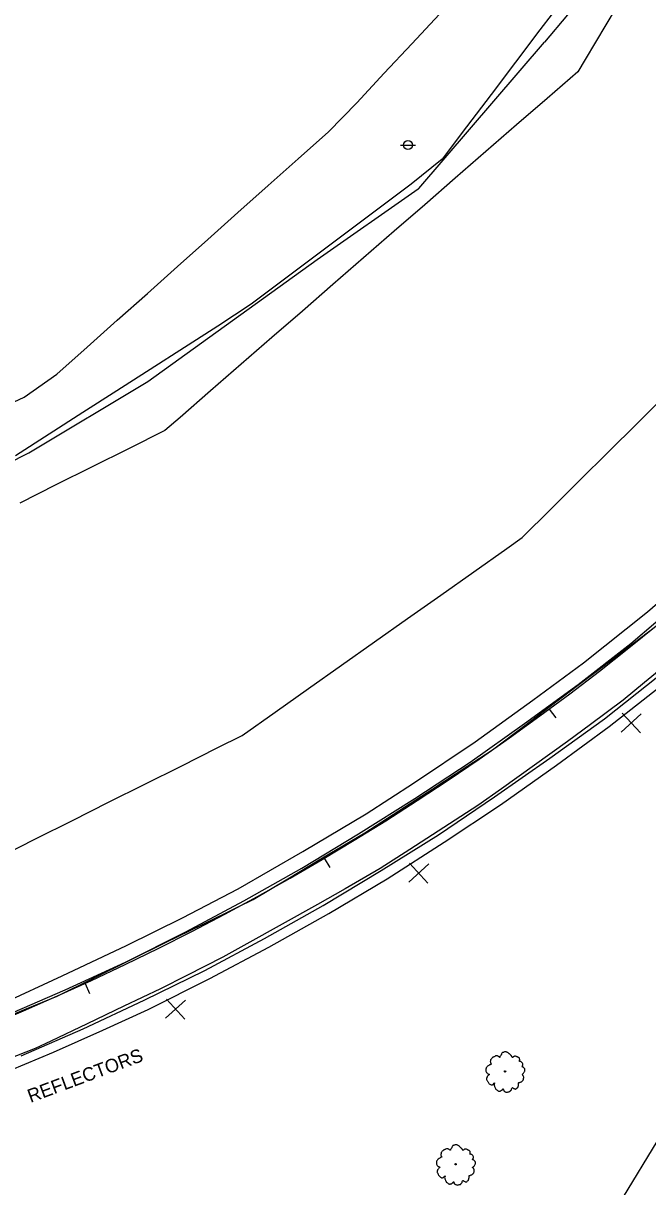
# Model space of a CAD drawing. Extents: x 2132221 to 2141942, y 535736 to 547298.
# Drawn here: x 2138327.6 to 2138558.7, y 541583.2 to 542013.9 of the extents above; entities that cross this region are included whole.
import ezdxf

# ---------------------------------------------------------------- set-up
doc = ezdxf.new("R2010")
doc.units = 0
for name, color, linetype in [('RD_EX_Conc', 7, 'Continuous'), ('RD_EX_Driveway', 7, 'Continuous'), ('RD_EX_Fence_Other', 7, 'Continuous'), ('RD_EX_Misc', 7, 'Continuous'), ('RD_EX_Misc_txCode', 7, 'Continuous'), ('RD_EX_Road', 7, 'Continuous'), ('RD_EX_SU_Pole', 7, 'Continuous'), ('RD_EX_VEG', 7, 'Continuous'), ('RD_HC_Cl', 7, 'Continuous'), ('RD_HC_Data_Tic', 7, 'Continuous')]:
    doc.layers.add(name, color=color, linetype=linetype)

msp = doc.modelspace()

# ---------------------------------------------------------------- linework, layer by layer
at = {"layer": 'RD_EX_Conc'}
for points in [[(2138320.66, 541646.24), (2138343.12, 541656.01), (2138365.46, 541666.32), (2138387.76, 541677.52), (2138409.22, 541688.97), (2138430.74, 541701.11), (2138451.71, 541713.76), (2138472.54, 541726.85), (2138492.99, 541740.37), (2138513.17, 541754.66), (2138532.93, 541769.02), (2138552.43, 541784.26), (2138571.02, 541800.11), (2138589.56, 541816.64), (2138607.73, 541833.33), (2138625.65, 541850.53), (2138634.91, 541859.67)], [(2138326.85, 541631.63), (2138349.75, 541641.63), (2138372.34, 541652.17), (2138394.8, 541663.21), (2138416.86, 541675.11), (2138438.6, 541687.28), (2138460.13, 541700.22), (2138481.26, 541713.49), (2138501.99, 541727.45), (2138522.49, 541741.75), (2138542.74, 541756.38), (2138562.52, 541772.02), (2138581.55, 541788.07), (2138600.17, 541804.67), (2138618.62, 541821.66), (2138636.61, 541838.98), (2138654.13, 541856.83)]]:
    msp.add_lwpolyline(points, dxfattribs=at)
at = {"layer": 'RD_EX_Driveway'}
for points in [[(2138527.91, 542023.36), (2138518.86, 542011.39), (2138509.82, 541999.43), (2138500.77, 541987.46), (2138491.72, 541975.5), (2138482.68, 541963.53), (2138471.18, 541954.28), (2138459.34, 541945.4), (2138447.51, 541936.53), (2138423.83, 541918.78), (2138411.99, 541909.91), (2138399.65, 541901.72), (2138362.19, 541877.75), (2138349.7, 541869.76), (2138337.21, 541861.77), (2138324.72, 541853.78)], [(2138314.31, 541869.21), (2138327.93, 541875.41), (2138340.03, 541883.96), (2138351.2, 541893.94), (2138362.37, 541903.91), (2138373.54, 541913.88), (2138384.71, 541923.85), (2138395.88, 541933.82), (2138407.05, 541943.79), (2138418.22, 541953.76), (2138429.38, 541963.73), (2138440.55, 541973.7), (2138451.05, 541984.36), (2138461.24, 541995.33), (2138471.43, 542006.3), (2138481.63, 542017.27)]]:
    msp.add_lwpolyline(points, dxfattribs=at)
at = {"layer": 'RD_EX_Fence_Other'}
msp.add_line((2138473.96, 541952.65), (2138520.49, 542006.82), dxfattribs=at)
for points in [[(2138676.9, 542216.89), (2138642.7, 542168.03), (2138605.66, 542115.76), (2138571.62, 542067.73), (2138520.49, 542006.82)], [(2138289.5, 541834.44), (2138329.69, 541854.79), (2138373.73, 541881.26), (2138436.34, 541926.45), (2138473.83, 541952.55), (2138473.96, 541952.65)]]:
    msp.add_lwpolyline(points, dxfattribs=at)
at = {"layer": 'RD_EX_Misc'}
for p, q in [((2138548.95, 541751.46), (2138556.3, 541758.24)), ((2138549.24, 541758.53), (2138556.02, 541751.18)), ((2138470.33, 541695.87), (2138477.68, 541702.65)), ((2138470.61, 541702.93), (2138477.39, 541695.59)), ((2138380.3, 541645.5), (2138387.65, 541652.28)), ((2138380.58, 541652.56), (2138387.36, 541645.21))]:
    msp.add_line(p, q, dxfattribs=at)
for points in [[(2138314.78, 541643.23), (2138328.64, 541648.96), (2138340.15, 541653.72), (2138353.6, 541660.36), (2138367.05, 541667), (2138380.5, 541673.64), (2138393.95, 541680.28), (2138407.4, 541686.92), (2138412.65, 541689.51), (2138425.53, 541697.19), (2138438.41, 541704.87), (2138451.3, 541712.55), (2138454.04, 541714.19), (2138466.62, 541722.36), (2138479.2, 541730.52), (2138491.78, 541738.69), (2138501.3, 541744.87), (2138513.26, 541753.93), (2138525.22, 541762.98), (2138537.17, 541772.04), (2138549.13, 541781.09), (2138561.09, 541790.15)], [(2138569.14, 541779.31), (2138557.56, 541769.78), (2138549.64, 541763.26), (2138537.61, 541754.3), (2138529.04, 541747.92), (2138516.83, 541739.22), (2138504.61, 541730.51), (2138495.84, 541724.26), (2138483.24, 541716.12), (2138470.64, 541707.98), (2138459.74, 541700.93), (2138446.73, 541693.46), (2138436.54, 541687.61), (2138423.43, 541680.33), (2138410.32, 541673.05), (2138401.51, 541668.15), (2138388.15, 541661.34), (2138378.42, 541656.38), (2138364.86, 541649.95), (2138351.31, 541643.52), (2138337.76, 541637.09), (2138332.02, 541634.37), (2138318.05, 541628.92)]]:
    msp.add_lwpolyline(points, dxfattribs=at)
at = {"layer": 'RD_EX_Road'}
for points in [[(2138319.72, 541650.84), (2138341.99, 541661.22), (2138365.85, 541672.43), (2138386.58, 541682.71), (2138407.18, 541693.44), (2138431.12, 541707.27), (2138454.48, 541721.2), (2138472.09, 541732.56), (2138494.83, 541747.89), (2138516.25, 541763.27), (2138534.97, 541777.14), (2138558.6, 541796.04), (2138579.91, 541814.38), (2138598.67, 541831.29), (2138617.88, 541849.47), (2138633.25, 541864.69), (2138648.79, 541880.72)], [(2138317.42, 541624.05), (2138338.77, 541633.03), (2138357.11, 541641.14), (2138373.84, 541648.73), (2138396.68, 541660.2), (2138418.52, 541671.85), (2138440.73, 541684.35), (2138462.3, 541697.15), (2138483.42, 541710.68), (2138504.29, 541724.54), (2138524.92, 541739.2), (2138544.46, 541753.5), (2138565.11, 541769.66), (2138581.74, 541783.59), (2138602.69, 541801.88), (2138618.54, 541816.61), (2138639.24, 541836.38), (2138662.83, 541860.24)], [(2138548.1, 541576.55), (2138563.93, 541602.75), (2138573.59, 541618.82), (2138583.77, 541636.3), (2138596.7, 541657.83), (2138601.61, 541666.1), (2138613.51, 541685.67), (2138628.6, 541710.63), (2138640.94, 541731.58), (2138653.63, 541752.56), (2138665.67, 541772.73), (2138676.11, 541790.53), (2138687.24, 541808.93), (2138697.28, 541825.4)]]:
    msp.add_lwpolyline(points, dxfattribs=at)
at = {"layer": 'RD_EX_SU_Pole'}
msp.add_line((2138467.23, 541968.75), (2138472.73, 541968.75), dxfattribs=at)
msp.add_circle((2138469.99, 541968.76), 1.65, dxfattribs=at)
at = {"layer": 'RD_EX_VEG'}
for points in [[(2138550.85, 542026.23), (2138543.19, 542013.34), (2138535.52, 542000.45), (2138532.81, 541995.9), (2138521.49, 541986.06), (2138510.16, 541976.22), (2138498.84, 541966.38), (2138487.52, 541956.54), (2138476.2, 541946.7), (2138464.88, 541936.86), (2138453.56, 541927.02), (2138442.24, 541917.18), (2138430.91, 541907.34), (2138419.59, 541897.5), (2138408.27, 541887.66), (2138396.95, 541877.82), (2138385.63, 541867.98), (2138379.96, 541863.05), (2138366.54, 541856.35), (2138353.12, 541849.64), (2138339.7, 541842.94), (2138326.29, 541836.23)], [(2138318.95, 541705.32), (2138332.37, 541712.04), (2138345.78, 541718.75), (2138359.19, 541725.47), (2138372.6, 541732.19), (2138386.01, 541738.91), (2138399.42, 541745.63), (2138408.62, 541750.23), (2138420.87, 541758.89), (2138433.12, 541767.54), (2138445.37, 541776.2), (2138457.62, 541784.86), (2138469.88, 541793.51), (2138482.13, 541802.17), (2138494.38, 541810.82), (2138506.63, 541819.48), (2138512.25, 541823.45), (2138522.89, 541834.02), (2138533.54, 541844.6), (2138544.18, 541855.17), (2138554.82, 541865.74), (2138565.46, 541876.31)]]:
    msp.add_lwpolyline(points, dxfattribs=at)
for centre, radius in [((2138505.95, 541625.86), 0.25), ((2138505.92, 541625.85), 0.0001), ((2138487.64, 541591.46), 0.25), ((2138487.62, 541591.46), 0.0001)]:
    msp.add_circle(centre, radius, dxfattribs=at)
for points in [[(2138511.31, 541630.61), (2138511.12, 541630.85), (2138510.83, 541631.02), (2138510.59, 541631.14), (2138510.38, 541631.25), (2138510.15, 541631.35), (2138509.82, 541631.45), (2138509.52, 541631.48), (2138509.25, 541631.41), (2138509.05, 541631.29), (2138508.82, 541631.14), (2138508.69, 541631.02), (2138508.59, 541631.1), (2138508.5, 541631.22), (2138508.39, 541631.46), (2138508.22, 541631.64), (2138508.05, 541631.83), (2138507.79, 541632.07), (2138507.56, 541632.32), (2138507.33, 541632.49), (2138507.08, 541632.7), (2138506.73, 541632.89), (2138506.4, 541633.06), (2138506.02, 541633.11), (2138505.5, 541632.97), (2138505.15, 541632.83), (2138504.87, 541632.77), (2138504.64, 541632.36), (2138504.5, 541631.99), (2138504.37, 541631.84), (2138504.11, 541631.49), (2138504.01, 541631.27), (2138503.95, 541631.04), (2138503.88, 541631.08), (2138503.59, 541631.32), (2138503.31, 541631.47), (2138502.86, 541631.63), (2138502.54, 541631.65), (2138502.24, 541631.5), (2138501.96, 541631.28), (2138501.75, 541631.22), (2138501.49, 541631.09), (2138501.42, 541631.05), (2138501.15, 541630.87), (2138500.89, 541630.49), (2138500.65, 541630.24), (2138500.56, 541629.99), (2138500.54, 541629.76), (2138500.47, 541629.47), (2138500.58, 541629.02), (2138500.72, 541628.71), (2138500.84, 541628.55), (2138500.36, 541628.34), (2138500.06, 541628.14), (2138499.69, 541627.96), (2138499.63, 541627.91), (2138499.25, 541627.62), (2138499.11, 541627.29), (2138498.88, 541626.99), (2138498.84, 541626.7), (2138498.8, 541626.3), (2138498.86, 541625.91), (2138499.11, 541625.46), (2138499.39, 541625.18), (2138499.91, 541624.87), (2138500.14, 541624.74), (2138499.99, 541624.64), (2138499.73, 541624.37), (2138499.42, 541624.08), (2138499.28, 541623.75), (2138499.15, 541623.49), (2138499.07, 541623.21), (2138499.12, 541622.82), (2138499.34, 541622.47), (2138499.51, 541622.06), (2138499.76, 541621.68), (2138500.08, 541621.29), (2138500.6, 541620.96), (2138500.88, 541620.84), (2138501.08, 541620.88), (2138501.49, 541620.99), (2138501.62, 541621.18), (2138502.08, 541621.57), (2138502.02, 541621.37), (2138501.88, 541621.01), (2138501.99, 541620.44), (2138502.14, 541620.03), (2138502.35, 541619.57), (2138502.5, 541619.3), (2138502.87, 541619.01), (2138503.18, 541618.78), (2138503.53, 541618.59), (2138503.93, 541618.55), (2138504.25, 541618.61), (2138504.49, 541618.76), (2138504.82, 541618.96), (2138504.98, 541619.04)], [(2138504.98, 541619.04), (2138505.06, 541619.22), (2138505.21, 541619.42), (2138505.24, 541619.35), (2138505.32, 541619.19), (2138505.42, 541618.9), (2138505.51, 541618.68), (2138505.75, 541618.46), (2138506.01, 541618.33), (2138506.52, 541618.18), (2138507.05, 541618.3), (2138507.53, 541618.37), (2138507.82, 541618.54), (2138507.95, 541618.73), (2138508.31, 541619.08), (2138508.35, 541619.4), (2138508.41, 541619.52), (2138508.64, 541619.87), (2138508.73, 541619.84), (2138508.95, 541619.68), (2138509.29, 541619.48), (2138509.57, 541619.37), (2138509.85, 541619.32), (2138510.07, 541619.42), (2138510.35, 541619.71), (2138510.67, 541619.94), (2138510.73, 541620.1), (2138510.78, 541620.27), (2138510.87, 541620.46), (2138510.88, 541620.68), (2138510.92, 541620.85), (2138510.93, 541620.99), (2138510.96, 541621.19), (2138510.93, 541621.4), (2138510.86, 541621.54), (2138510.94, 541621.68), (2138511.19, 541621.71), (2138511.3, 541621.74), (2138511.48, 541621.87), (2138511.89, 541621.94), (2138512.22, 541622.18), (2138512.5, 541622.5), (2138512.66, 541622.72), (2138512.76, 541623.02), (2138512.81, 541623.34), (2138512.86, 541623.55), (2138512.83, 541623.76), (2138512.7, 541624.08), (2138512.57, 541624.3), (2138512.33, 541624.56), (2138512.23, 541624.74), (2138512.29, 541624.76), (2138512.4, 541624.86), (2138512.6, 541625.04), (2138512.88, 541625.4), (2138513.15, 541625.85), (2138513.16, 541625.87), (2138513.28, 541626.11), (2138513.27, 541626.41), (2138513.23, 541626.61), (2138513.19, 541626.84), (2138513.04, 541627.04), (2138512.83, 541627.26), (2138512.61, 541627.43), (2138512.4, 541627.51), (2138512.19, 541627.55), (2138512.25, 541627.71), (2138512.4, 541627.99), (2138512.48, 541628.13), (2138512.51, 541628.35), (2138512.5, 541628.66), (2138512.29, 541629.07), (2138511.81, 541629.48), (2138511.46, 541629.56), (2138511.23, 541629.56), (2138511.29, 541629.68), (2138511.3, 541629.96), (2138511.36, 541630.15), (2138511.33, 541630.37), (2138511.3, 541630.54), (2138511.27, 541630.65)], [(2138493, 541596.22), (2138492.82, 541596.46), (2138492.53, 541596.63), (2138492.28, 541596.75), (2138492.08, 541596.86), (2138491.85, 541596.96), (2138491.52, 541597.06), (2138491.22, 541597.09), (2138490.95, 541597.01), (2138490.75, 541596.9), (2138490.51, 541596.75), (2138490.39, 541596.63), (2138490.28, 541596.7), (2138490.2, 541596.83), (2138490.09, 541597.07), (2138489.92, 541597.25), (2138489.75, 541597.43), (2138489.49, 541597.67), (2138489.25, 541597.93), (2138489.03, 541598.1), (2138488.77, 541598.3), (2138488.43, 541598.5), (2138488.1, 541598.67), (2138487.71, 541598.72), (2138487.19, 541598.58), (2138486.85, 541598.44), (2138486.57, 541598.38), (2138486.34, 541597.96), (2138486.2, 541597.6), (2138486.07, 541597.44), (2138485.81, 541597.1), (2138485.71, 541596.87), (2138485.65, 541596.65), (2138485.58, 541596.68), (2138485.29, 541596.93), (2138485.01, 541597.08), (2138484.56, 541597.24), (2138484.24, 541597.25), (2138483.93, 541597.11), (2138483.66, 541596.89), (2138483.44, 541596.83), (2138483.19, 541596.69), (2138483.12, 541596.66), (2138482.85, 541596.48), (2138482.58, 541596.1), (2138482.34, 541595.84), (2138482.26, 541595.6), (2138482.23, 541595.37), (2138482.17, 541595.07), (2138482.27, 541594.63), (2138482.42, 541594.32), (2138482.54, 541594.16), (2138482.05, 541593.95), (2138481.76, 541593.75), (2138481.38, 541593.57), (2138481.33, 541593.52), (2138480.94, 541593.23), (2138480.81, 541592.9), (2138480.58, 541592.59), (2138480.53, 541592.31), (2138480.5, 541591.91), (2138480.56, 541591.51), (2138480.8, 541591.06), (2138481.09, 541590.79), (2138481.61, 541590.48), (2138481.83, 541590.35), (2138481.69, 541590.25), (2138481.43, 541589.98), (2138481.12, 541589.69), (2138480.98, 541589.36), (2138480.85, 541589.1), (2138480.76, 541588.82), (2138480.82, 541588.43), (2138481.03, 541588.08), (2138481.21, 541587.67), (2138481.46, 541587.29), (2138481.78, 541586.9), (2138482.3, 541586.56), (2138482.58, 541586.44), (2138482.77, 541586.49), (2138483.18, 541586.6), (2138483.32, 541586.79), (2138483.77, 541587.17), (2138483.71, 541586.98), (2138483.57, 541586.62), (2138483.69, 541586.05), (2138483.83, 541585.63), (2138484.05, 541585.18), (2138484.19, 541584.91), (2138484.57, 541584.61), (2138484.88, 541584.39), (2138485.23, 541584.2), (2138485.63, 541584.16), (2138485.95, 541584.22), (2138486.19, 541584.37), (2138486.51, 541584.57), (2138486.68, 541584.65)], [(2138486.68, 541584.65), (2138486.75, 541584.82), (2138486.9, 541585.03), (2138486.94, 541584.96), (2138487.02, 541584.79), (2138487.11, 541584.51), (2138487.21, 541584.29), (2138487.45, 541584.07), (2138487.71, 541583.94), (2138488.21, 541583.79), (2138488.75, 541583.91), (2138489.23, 541583.98), (2138489.52, 541584.14), (2138489.65, 541584.33), (2138490, 541584.69), (2138490.05, 541585.01), (2138490.11, 541585.13), (2138490.34, 541585.47), (2138490.42, 541585.45), (2138490.65, 541585.28), (2138490.99, 541585.09), (2138491.27, 541584.97), (2138491.55, 541584.93), (2138491.77, 541585.02), (2138492.04, 541585.31), (2138492.37, 541585.55), (2138492.43, 541585.7), (2138492.47, 541585.88), (2138492.57, 541586.07), (2138492.58, 541586.28), (2138492.62, 541586.46), (2138492.63, 541586.6), (2138492.65, 541586.79), (2138492.63, 541587.01), (2138492.56, 541587.15), (2138492.64, 541587.29), (2138492.89, 541587.31), (2138492.99, 541587.34), (2138493.18, 541587.48), (2138493.59, 541587.55), (2138493.91, 541587.78), (2138494.19, 541588.11), (2138494.36, 541588.33), (2138494.46, 541588.63), (2138494.51, 541588.94), (2138494.55, 541589.15), (2138494.53, 541589.37), (2138494.4, 541589.69), (2138494.27, 541589.91), (2138494.03, 541590.17), (2138493.93, 541590.35), (2138493.98, 541590.36), (2138494.09, 541590.46), (2138494.3, 541590.65), (2138494.58, 541591.01), (2138494.84, 541591.46), (2138494.86, 541591.48), (2138494.98, 541591.72), (2138494.97, 541592.02), (2138494.93, 541592.22), (2138494.88, 541592.45), (2138494.73, 541592.65), (2138494.53, 541592.87), (2138494.31, 541593.04), (2138494.1, 541593.12), (2138493.89, 541593.16), (2138493.95, 541593.32), (2138494.1, 541593.59), (2138494.18, 541593.73), (2138494.2, 541593.96), (2138494.2, 541594.26), (2138493.98, 541594.68), (2138493.51, 541595.09), (2138493.16, 541595.17), (2138492.93, 541595.16), (2138492.98, 541595.28), (2138492.99, 541595.57), (2138493.06, 541595.76), (2138493.03, 541595.97), (2138493, 541596.15), (2138492.97, 541596.26)]]:
    msp.add_spline(points, degree=3, dxfattribs=at)
at = {"layer": 'RD_HC_Cl'}
msp.add_arc((2137944.04, 542541.74), 972.38, 220.32405, 325.12405, dxfattribs=at)
at = {"layer": 'RD_HC_Data_Tic'}
for p, q in [((2138522.31, 541760), (2138524.69, 541756.78)), ((2138439, 541704.76), (2138441.04, 541701.32)), ((2138350.46, 541658.37), (2138352.14, 541654.74))]:
    msp.add_line(p, q, dxfattribs=at)

# ---------------------------------------------------------------- texts
at = {"layer": 'RD_EX_Misc_txCode'}
msp.add_text('REFLECTORS', height=5, rotation=20.4271, dxfattribs=at).set_placement((2138330.3, 541614.15))

doc.saveas('drawing.dxf')
